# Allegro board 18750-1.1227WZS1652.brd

Outline 227 x 157 mm; copper layers: TOP, L2GND, L3, L4VCC, L5, L6, L7GND, BOTTOM. Coordinates in mm from the lower left corner of the outline.

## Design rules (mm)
constraint set DEFAULT: min track width 0.127, pair gap 0.102
net group 00_POWER_25M: nets PQ3802_1 PSID_DISABLE#_R_C
net group 00_POWER_1600M: nets XVDD_R1 XVDD_R2
net group DDR4_A_BA_40-MW: nets M_A_BA0 M_A_BA1
net group DDR4_A_BG_40-MW: nets M_A_BG0 M_A_BG1
net group DDR4_A_ODT: nets M_A_DIMA_ODT0 M_A_DIMA_ODT1
net group DDR4_B_BA_40-MW: nets M_B_BA0 M_B_BA1
net group DDR4_B_BG_40-MW: nets M_B_BG0 M_B_BG1
net group DDR4_B_ODT: nets M_B_DIMB_ODT0 M_B_DIMB_ODT1
net group DDR4_VREF_40: nets V_SM_VREF_CNTA V_SM_VREF_CNTB
net group MEM_SMBCLK: nets MEM_SMBCLK PCH_SMBCLK
net group MEM_SMBDATA: nets MEM_SMBDATA PCH_SMBDATA
net group PWR_CHG_CSONP-DIFF1: nets PWR_CHG_CSON_RR PWR_CHG_CSOP_RR
net group T8-MW: nets CMP_VIN0 CMP_VIN0_R
net group USB_CC_15M: nets USBC1_CC1_CONN USBC1_CC2_CONN
net group 00_POWER_5M: nets 3D3V_LAN_CT2 3V5V_CT1 3V5V_CT2 AON_CT_2 AUD_PC_BEEP AUD_PC_BEEP_C BEEP HDA_SPKR_R KBC_BEEP_R LPS_SW LPS_SW_A LPS_SW_C LPS_SW_D SPKR VGA_CT_1 VGA_NVVDD
net group 00_POWER_10M: nets 1D0V_VCCA_XTAL 1D0V_VCCAMPHYPLL 1D0V_VCCDSW +5V_AVDD +SDC_IN_SW_R1 BMON22 CNV_WT_RCOMP FP_3D3V GSENSOR_CS HW_ACAV_IN0 HW_ACAVIN_NB0 I_BATT LDO1_CAP LDO2_CAP LDO3_CAP MIC_CAP PWR_VGA_NVDD_SS PWR_VGA_NVVDD_VSEN PWR_VGA_NVVDD_VSNS/SS
net group 00_POWER_10M_POWER: nets 3D3V_GSEN2 3D3V_MUX 3D3V_MUX2 3D3V_MUX_VCC AC_IN#_G AD_OFF_R AMBER_LED_BAT BAT_AMBER BAT_WHITE LAN_LED0 LAN_LED0_Q LAN_LED0_R PD_VCCD PWR_1D05V_PFM# PWR_1D05V_SS PWR_1D05V_TON PWR_1D35V_BYP PWR_1D35V_IMAX PWR_3D3V_VOUT PWR_5V_VOUT PWR_CHG_ACIN PWR_CHG_ADP/ACIN PWR_CHG_AIN PWR_CHG_AIN_R PWR_CHG_AMON PWR_CHG_ASGATE PWR_CHG_ASGATE/NTC PWR_CHG_BATGONE PWR_CHG_CMRSC PWR_CHG_COMP PWR_CHG_COMP_R PWR_CHG_DCIN PWR_CHG_DCIN_R PWR_CHG_NTC PWR_CHG_OTGEN PWR_CHG_OTGPG PWR_CHG_PROG PWR_CHG_VBAT1 PWR_VCCGT_COMP PWR_VCCGT_COMP1 PWR_VCCGT_FCCM# PWR_VCCGT_FCCM#_RA PWR_VCCGT_FCCM#_RB PWR_VCCGT_IMON PWR_VCCGT_ISEN1 PWR_VCCGT_ISEN2 PWR_VCCGT_ISUMN PWR_VCCGT_ISUMN_P_1 PWR_VCCGT_ISUMN_P_2 PWR_VCCGT_ISUMN_RC PWR_VCCGT_ISUMNB PWR_VCCGT_ISUMP PWR_VCCGT_NTC PWR_VCCGT_NTC1 PWR_VCCGT_PWMA PWR_VCCGT_PWMA_RA PWR_VCCGT_PWMB PWR_VCCGT_PWMB_RA PWR_VCCGT_RTN PWR_VCCSA_COMP PWR_VCCSA_COMP_RC PWR_VCCSA_FCCM PWR_VCCSA_IMON PWR_VCCSA_ISUMN PWR_VCCSA_ISUMN_P_1 PWR_VCCSA_ISUMN_P_2 PWR_VCCSA_ISUMN_RC PWR_VCCSA_ISUMNB PWR_VCCSA_ISUMP PWR_VCCSA_PWM PWR_VCCSA_RTN PWR_VCORE_COMP PWR_VCORE_COMP1 PWR_VCORE_FCCM# PWR_VCORE_FCCM#_R PWR_VCORE_IMON PWR_VCORE_ISUMN PWR_VCORE_ISUMN_P_1 PWR_VCORE_ISUMN_P_2 PWR_VCORE_ISUMN_RC PWR_VCORE_ISUMNA PWR_VCORE_ISUMP PWR_VCORE_NTC PWR_VCORE_NTC1 PWR_VCORE_PROG1 PWR_VCORE_PROG2 PWR_VCORE_PWM PWR_VCORE_PWM_R PWR_VCORE_RTN PWR_VCORE_VR PWR_VDDQ_CS PWR_VDDQ_FB PWR_VDDQ_TON PWR_VDDQ_VDDQ PWR_VGA_CORE_EN# PWR_VGA_CORE_PSI PWR_VGA_CORE_VID PWR_VGA_NVVDD_REFADJ PWR_VGA_NVVDD_REFADJ_R PWR_VGA_NVVDD_REFIN PWR_VGA_NVVDD_REFIN_R PWR_VGA_NVVDD_TON PWR_VGA_NVVDD_TON_1 PWR_VGA_NVVDD_VREF PWR_VGA_NVVDD_VSEN_N PWR_VGA_NVVDD_VSEN_P VDD WHITE_LED_BAT
net group 00_POWER_15M_FB_POWER: nets PWR_1D05V_FB PWR_1D05V_FB_A PWR_1D8V_FB PWR_1D35V_VFB PWR_1D35V_VFB1 PWR_1V_VGA_FB PWR_2D5V_FB PWR_3D3V_FB PWR_3D3V_FB2 PWR_5V_FB PWR_5V_FB_A PWR_VCCGT_FB PWR_VCCGT_FB1 PWR_VCCGT_FB2 PWR_VCCGT_FB_RC PWR_VCCSA_FB PWR_VCCSA_FB1 PWR_VCCSA_FB2 PWR_VCCSA_FB_RC PWR_VCORE_FB PWR_VCORE_FB1 PWR_VCORE_FB2 PWR_VCORE_FB_RC
net group 00_POWER_20M: nets 1D8V_AVDD2 1D24V_VCCDPHY_EC 3D3V_RTC 3D3V_RTC_SYS 3D3V_SPIVCC1 3D3V_TPM 5V_IRLED +RTC_CELL_VBAT +RTC_VCC +V_VREF_PATH2 GPCPLL_AVDD VDD10 VID_PLLVDD VREF_CPU
net group 00_POWER_20M_20M_POWER: nets PWR_1D35V_BOOT_R PWR_3D3V_BOOT PWR_3D3V_BOOT_A PWR_5V_BOOT PWR_5V_BOOT_A PWR_CHG_ASGATE22 PWR_CHG_BGATE PWR_CHG_BGATE_22 PWR_CHG_BT2_R PWR_VCCGT_BOOTA PWR_VCCGT_BOOTA_RC PWR_VCCGT_BOOTB PWR_VCCGT_BOOTB_RC PWR_VCCGT_BOOTRA PWR_VCCGT_BOOTRB PWR_VCCGT_SNB1 PWR_VCCGT_SNB2 PWR_VCCSA_BST PWR_VCCSA_BST_RC PWR_VCORE_BOOT_RC PWR_VCORE_BOOTR PWR_VCORE_SNB PWR_VDDQ_BOOT PWR_VDDQ_BOOTA PWR_VDDQ_BOOTB PWR_VDDQ_SNB PWR_VGA_NVVDD_BOOT1_A PWR_VGA_NVVDD_BOOT2_A
net group 00_POWER_20M_POWER: nets 5V_AUX_S5 5V_VCONN_P1_CCG4 +5V_KB_BL CPVDD KB_BL_CTRL# PWR_5V_LDO PWR_VCCGT_VCCDA PWR_VCORE_VCC PWR_VCORE_VIN
net group 00_POWER_30M: nets +3V_1D8V_DVDD
net group 00_POWER_30M_20M_POWER: nets PWR_CHG_HG1_R PWR_CHG_HG2_R PWR_CHG_LGATE2 PWR_CHG_SNB
net group 00_POWER_40M: nets 5V_HDMI +1.8VALW_EC DC_IN_OFF FB_CAL_PD_VDDQ FB_CAL_PU_GND FB_CAL_TERM_GND PQ4348_D PU4348_G PWR_VDDQ_VTTREF
net group 00_POWER_80M: nets 1D8V_AON_S0_DISCHG 1D8V_VGA_S0_DISCHG 1D35V_VGA_S0_DISCHG VGA_CORE_DISCHG
net group 3D5MIL_NO_TP: nets FBA_MF1
net group AUDIO_8M: nets MIC2_VREFO
net group AUDIO_12MIL: nets CPVEE
net group AUDIO_12MIL(2): nets AUD_HP1_JACK_L AUD_HP1_JACK_L1 AUD_HP1_JACK_R AUD_HP1_JACK_R1 AUD_PORTA_L_HPMIC1 AUD_PORTA_R_HPMIC1
net group AUDIO_BEEP_10MIL: nets AUD_HPJD_N AUD_SENSE AUD_VREF CBN CBP JACK_PLUG JACK_PLUG_DET LINE1-L_C LINE1-L_R LINE1_L LINE1_R LINE1_VREFO LINE1_VREFO_D1 LINE1_VREFO_D2
net group AUDIO_BITCLK_50-MW: nets HDA_RST_N_CPU
net group AUDIO_SLEEVE_40MIL: nets SLEEVE_R
net group CLK_50-MWS: nets CLKIN_XTAL_LCP PULSAR_38P4M_REFCLK SUS_CLK SUSACK#_R SUSCLK_WLAN VIDEO_CLK_XTAL_SS
net group CNV: nets CNV_MFUART2_RXD CNV_MFUART2_TXD CNV_PA_BLANKING
net group COMP_20MIL: nets CFG_RCOMP SM_RCOMP_0 SM_RCOMP_1 SM_RCOMP_2
net group CPU_50-MWS: nets CMP_VOUT0 LPS_SW_R SM_DRAMRST#_CPU TS#_DIMM0_1 TS#_DIMM1_1 VGA_CORE_VID
net group CRT_AUX_CPU_N: nets CRT_AUX_CPU_N_R
net group CRT_AUX_CPU_P: nets CRT_AUX_CPU_P_R
net group CRT_DDI_TX_N0: nets DP2_DEMUX_OUT2_D0N
net group CRT_DDI_TX_P0: nets DP2_DEMUX_OUT2_D0P
net group DDR4_A_CMD_40-MW: nets M_A_A0 M_A_A1 M_A_A2 M_A_A3 M_A_A4 M_A_A5 M_A_A6 M_A_A7 M_A_A8 M_A_A9 M_A_A10 M_A_A11 M_A_A12 M_A_A13 M_A_A14 M_A_A15 M_A_A16 M_A_ACT_N M_A_ALERT_N M_A_PARITY
net group DDR4_A_DATA_00_50-MW: nets M_A_DQ0 M_A_DQ1 M_A_DQ2 M_A_DQ3 M_A_DQ4 M_A_DQ5 M_A_DQ6 M_A_DQ7
net group DDR4_A_DATA_01_50-MW: nets M_A_DQ8 M_A_DQ9 M_A_DQ10 M_A_DQ11 M_A_DQ12 M_A_DQ13 M_A_DQ14 M_A_DQ15
net group DDR4_A_DATA_02_50-MW: nets M_A_DQ16 M_A_DQ17 M_A_DQ18 M_A_DQ19 M_A_DQ20 M_A_DQ21 M_A_DQ22 M_A_DQ23
net group DDR4_A_DATA_03_50-MW: nets M_A_DQ24 M_A_DQ25 M_A_DQ26 M_A_DQ27 M_A_DQ28 M_A_DQ29 M_A_DQ30 M_A_DQ31
net group DDR4_A_DATA_04_50--MW: nets M_A_DQ32 M_A_DQ33 M_A_DQ34 M_A_DQ35 M_A_DQ36 M_A_DQ37 M_A_DQ38 M_A_DQ39
net group DDR4_A_DATA_05_50-MW: nets M_A_DQ40 M_A_DQ41 M_A_DQ42 M_A_DQ43 M_A_DQ44 M_A_DQ45 M_A_DQ46 M_A_DQ47
net group DDR4_A_DATA_06_50-MW: nets M_A_DQ48 M_A_DQ49 M_A_DQ50 M_A_DQ51 M_A_DQ52 M_A_DQ53 M_A_DQ54 M_A_DQ55
net group DDR4_A_DATA_07_50-MW: nets M_A_DQ56 M_A_DQ57 M_A_DQ58 M_A_DQ59 M_A_DQ60 M_A_DQ61 M_A_DQ62 M_A_DQ63
net group DDR4_B_CMD_40--MW: nets M_B_A0 M_B_A1 M_B_A2 M_B_A3 M_B_A4 M_B_A5 M_B_A6 M_B_A7 M_B_A8 M_B_A9 M_B_A10 M_B_A11 M_B_A12 M_B_A13 M_B_A14 M_B_A15 M_B_A16 M_B_ACT_N M_B_ALERT_N M_B_PARITY
net group DDR4_B_DATA_00_50-MW: nets M_B_DQ0 M_B_DQ1 M_B_DQ2 M_B_DQ3 M_B_DQ4 M_B_DQ5 M_B_DQ6 M_B_DQ7
net group DDR4_B_DATA_01_50-MW: nets M_B_DQ8 M_B_DQ9 M_B_DQ10 M_B_DQ11 M_B_DQ12 M_B_DQ13 M_B_DQ14 M_B_DQ15
net group DDR4_B_DATA_02_50-MW: nets M_B_DQ16 M_B_DQ17 M_B_DQ18 M_B_DQ19 M_B_DQ20 M_B_DQ21 M_B_DQ22 M_B_DQ23
net group DDR4_B_DATA_03_50-MW: nets M_B_DQ24 M_B_DQ25 M_B_DQ26 M_B_DQ27 M_B_DQ28 M_B_DQ29 M_B_DQ30 M_B_DQ31
net group DDR4_B_DATA_04_50-MW: nets M_B_DQ32 M_B_DQ33 M_B_DQ34 M_B_DQ35 M_B_DQ36 M_B_DQ37 M_B_DQ38 M_B_DQ39
net group DDR4_B_DATA_05_50-MW: nets M_B_DQ40 M_B_DQ41 M_B_DQ42 M_B_DQ43 M_B_DQ44 M_B_DQ45 M_B_DQ46 M_B_DQ47
net group DDR4_B_DATA_06_50-MW: nets M_B_DQ48 M_B_DQ49 M_B_DQ50 M_B_DQ51 M_B_DQ52 M_B_DQ53 M_B_DQ54 M_B_DQ55
net group DDR4_B_DATA_07_50-MW: nets M_B_DQ56 M_B_DQ57 M_B_DQ58 M_B_DQ59 M_B_DQ60 M_B_DQ61 M_B_DQ62 M_B_DQ63
net group DDR4_CKE: nets M_A_CKE0 M_A_CKE1 M_A_CS#0 M_A_CS#1 M_B_CKE0 M_B_CKE1 M_B_CS#0 M_B_CS#1
net group DIMM_SA: nets SA0_CHA_DIM0 SA0_CHB_DIM0 SA1_CHA_DIM0 SA1_CHB_DIM0 SA2_CHA_DIM0 SA2_CHB_DIM0
net group EPSI_50: nets ESPI_ALERT#
net group FBA_VREF: nets FBA0_VREFC FBA1_VREFC FBA_VREF_FET_L
net group GFX_PCIE_TX_C_N2: nets GFX_PCIE_TX_C_N2
net group GFX_PCIE_TX_C_P2: nets GFX_PCIE_TX_C_P2
net group GND: nets U9101_2_GND
net group KBC: nets KSI0 KSI1 KSI2 KSI3 KSI4 KSI5 KSI6 KSI7 KSO0 KSO1 KSO2 KSO3 KSO4 KSO5 KSO6 KSO7 KSO8 KSO9 KSO10 KSO11 KSO12 KSO13 KSO14 KSO15 KSO16
net group LAN_6M: nets FBA_MF0 FBA_SEN1 RSET
net group LAN_MDI0_N: nets MDO0-
net group LAN_MDI0_P: nets MDO0+
net group LAN_MDI1_N: nets MDO1-
net group LAN_MDI1_P: nets MDO1+
net group LAN_MDI2_N: nets MDO2-
net group LAN_MDI2_P: nets MDO2+
net group LAN_MDI3_N: nets MDO3-
net group LAN_MDI3_P: nets MDO3+
net group LED: nets BAT2_LED# CAP_LED# CAP_LED#_R PWR_LED# PWR_LED#_C PWR_LED#_Q PWR_LED#_R SATA_LED# SATA_LED#_D
net group LED_20MIL: nets C10_GATE CAP_LED CAP_LED_Q
net group OTHER_4MIL: nets 1D05V_S5_PWRGD 1D8V_AON_EN 1D8V_MAIN_EN 1D8V_MAIN_EN_D 1D8V_MAIN_EN_R 1D8V_MAIN_ENABLE 1D8V_VGA_DISC 1D35V_PGOOD 1D35V_VGA_EN# 1V_VGA_S0_EN 1V_VGA_S0_PG 3D3V_CAMERA_CT1 3D3V_TP_CT2 3V_5V_DSW_OK 3V_5V_EN 3V_5V_POK# 5V_VCONN_EN 20V_VCCPD_VBUS_R AC_DIS AC_PRESENT ACOK_IN_M AD_IA AD_OFF_L ALERT# ALWON AUX_EN_WOWL AUX_EN_WOWL_R AUX_ON BAT1_LED# BATT_WHITE_LED# BATT_WHITE_LED#_Q BKLT_CTRL BKLT_IN_EC BLON_OUT_C BLUETOOTH_EN BLUETOOTH_EN_R BOARD_ID BOARD_ID1 BPM_CPU_N0 BPM_CPU_N1 BPM_CPU_N2 BPM_CPU_N3 BREATH_LED# BT_PCMOUT_CLKREQ0 CAD_SNK_MUX CAM_EN CATERR#_CPU CCG4_FLIP# CCG4_I2C_INT# CCG4_ID_1 CFG0_DP_MUX CFG3 CFG4 CHG_AMBER_LED# CHG_AMBER_LED#_Q CHGR_PSYS_IMVP CLK_PCIE_LAN_REQ# CLK_PCIE_NVME_REQ# CLK_PCIE_PEG_REQ# CLK_PCIE_SD_REQ# CLK_PCIE_WLAN_REQ# CNVI_EN# CNVI_EN#_R CPU_DP1_HPD CPU_DP2_HPD CPU_DP_HPD_MUX CPU_DP_HPD_R CRT_DP_HPD CRT_DP_HPD_R CTL1 CTL2 CTL3 DBC_EN_R DBC_PANEL_EN DCBATOUT_LCD_PG DCBATOUT_LCD_PWRGD DDR4_DRAMRST# DGPU_HOLD_RST# DGPU_PWR_EN DGPU_PWR_EN_1 DGPU_PWR_EN_2 DGPU_PWROK DOCK_USB_EN_A DOCK_USB_EN_B DP2_HPD_CPU DPEQ0_A1 DPEQ1 EC_D_INHIB EDP_FHD_DET# EDP_FHD_DET#_R EDP_HPD EDP_HPD_CONN EDP_VDD_EN EQ0 EQ1 EXT_PWR_GATE# FALL_INT2 FBA_DEBUG0 FBA_DEBUG1 FFS_INT1 FFS_INT2 FFS_INT2_Q FLT_NXP3290 FP_EN# FPR_SCAN# GC6_FB_EN_GPU GC6_FB_EN_GPU_L GC6_FB_EN_GPU_R GC6_FB_EN_MCP GC6_THM_DIS GC6_THM_DIS#_EC GC6_THM_DIS#_PCH GPD11/LANPHYPC GPD_7 GPIO5_FRAME_LOCK# GPIO9_ALERT GPIO10_FBVREF GPIO11_LCD_VDD GPIO13_LCD_BLEN GPP_E23_STRAP GPP_H2_CLKREQ0 GPP_H21 GPP_H23 GPPC_H18_VCCIO_LPM GPU_CLKREQ# GPU_EVENT_GPU# GPU_EVENT_GPU#_R GPU_EVENT_MCP# GPU_PEX_RST# GPU_PEX_RST_HOLD GPU_PEX_RST_HOLD_GPU# GPU_ROM GSENSOR_SDO H_CPUPWRGD HDD_DET# HDD_DEVSLP HDD_DEVSLP_R HDMI_HPD_B HDMI_HPD_CON HOST_DEBUG_TX HOST_DEBUG_TX_CON HPDIN HW_ACAV_IN HW_ACAVIN_NB I2C_CTL_EN I2CEN I_ADP IC_DELAY ICSP_CLR ILIM_HI ILIM_LO ILIM_SEL INPUT3VSEL INT#_ITE8010 IO_DB_DET# IO_DB_DET#_EC IO_DB_DET#_GPPG5 IO_DB_DET#_R IR_CAM_DET# ISOLATE# IST_TRIG ITP_PMODE JIO3_PCIE_WAKE# KB_DET# KB_LED_BL_DET KB_LED_DET_C KB_LED_PWM KBC_PWRBTN# KBC_PWRBTN#_C L_BKLT_CTRL L_BKLT_EN L_BKLT_EN_L LAN_CABLE_DETECT_R_# LAN_WAKE# LANWAKE# LCD_BRIGHTNESS LCD_CBL_DET# LCD_TST LCD_TST_C LCD_VCC_TEST_EN LCDVDD_EN LCDVDD_PG LCDVDD_PWRGD LID_CL_SIO# LID_CLOSE#_C LOM_CABLE_DETECT# LOM_TCT M2_PCIE_LED# M2_SSD_PEDET MASK_SATA_LED# MCT0 MCT1 MCT2 MCT3 ME_FWP ME_FWP_R ME_SUS_PWR_ACK_R MESW1_B MODEL_ID MSATA_DEVSLP_R MUX_HPD_PD MUX_SAI MUX_SAO MUX_SBI MUX_SBO N12P_JTAG_TCK N12P_JTAG_TDI N12P_JTAG_TDO N12P_JTAG_TMS N12P_JTAG_TRST N12P_XTAL_OUTBUFF N92950396 NB_MUTE# NC_AUX_EN_WOWL_EC NRB_BIT NUVOTON_PP NVVDD_EN NVVDD_EN_1 NXP3290_FO NXP3290_ILIM NXP3290CAP OUT1_CA_DET OUT2_CA_DET OVERT_GPU# PANEL_BKEN PANEL_BKEN_EC PANEL_MONITOR PANEL_PWRGD_R PBAT_PRES1# PBAT_PRES# PC10 PC11 PC20 PC21 PCH_BATLOW# PCH_PLTRST# PCH_RSMRST# PCH_TPAN_VDD_EN PCH_WAKE# PCIE_LAN_WAKE# PCIE_WAKE# PD4403_A PD4403_K PD_SWD_CLK PD_VBUS_C_CTRL1 PD_VBUS_C_CTRL1_A PD_VBUS_C_CTRL1_R PD_VBUS_C_EN_A PD_VBUS_C_EN_B PD_VBUS_DISCHG PD_VBUS_DISCHG_N1 PD_XRES PDB_R PEQ PEX_TERMP PEX_TSTCLK_OUT PEX_TSTCLK_OUT# PIRQA# PLTRST#_CPU PM_LAN_ENABLE PM_RSMRST# PM_RSMRST#_M POWER_SW_IN# PQ4405_2 PQ4405_3 PQ4405_5 PQ4405_6 PQ4408_C PQ4408_E PQ4417_D PQ4417_G PQ4418_2 PQ4418_3 PQ4418_5 PQ4418_6 PRIM_PWRGD PROCHOT PROCHOT#_CPU PROCHOT#_CPU_R PROJECT_ID0 PROJECT_ID1 PROJECT_ID2 PROJECT_ID3 PTP_DIS# PURE_HW_SHUTDOWN# PWR_1D05V_EN PWR_1D8V_EN PWR_1D8V_PG PWR_1D35V_PGOOD PWR_2D5V_EN PWR_2D5V_PG PWR_3D3V_EN PWR_3D3V_EN1 PWR_5V_EN PWR_5V_EN1 PWR_BD_DET# PWR_CHG_ACOK PWR_CHG_PSYS PWR_LEVEL PWR_VDDQ_EN PWR_VDDQ_PG PWR_VGA_GDDR_EN PWR_VGA_GDDR_EN_L PWR_VGA_NVVDD_EN PWR_VGA_NVVDD_EN_R PWR_VGA_NVVDD_PG Q501_G Q5503_B Q5503_C Q5503_E Q5504_B Q5504_C Q5505_E Q6407_B Q6407_C RESET_OUT# RSMRST_PWRGD# RTC_3P3_EN_G RTC_DET# RTCRST_ON RUNPWROK SATA1_ODD_PRSNT# SATA_ODD_DA#_C SATA_ODD_PRSNT#_R SD_READ_MODE# SD_READ_MODE#_R SIO_EXT_SMI# SIO_EXT_WAKE# SIO_PWRBTN# SIO_RCIN# SIO_SLP_A# SIO_SLP_S0# SIO_SLP_S3# SIO_SLP_S4# SIO_SLP_S5# SKTOCC# SM_INTRUDER# SM_PGCNTL SM_PGCNTL_Q SSD2_DEVSLP SSD_DEVSLP SSD_DEVSLP_R SSD_SCP# SSEQ0_A0 SSEQ1 ST_GPIO ST_PP STRAP0 STRAP1 STRAP2 STRAP3 STRAP4 STRAP5 STRAP5_R STRAP_REF0_GND_N9 SW_PIN SYS_LED_MASK# SYS_PEX_RST_MON# SYS_PEX_RST_MON_GPU# SYS_PRES1# SYS_PWROK SYSPWR_PRES T_CRIT# TESTMODE THERM_SYS_SHDN# THERMTRIP#_CPU TOUCH_I2C_DET# TOUCH_PAD_INTR# TOUCH_PANEL_INTR# TOUCH_PANEL_PD# TOUCH_REPORT_SW TP_EN# TP_ON#_GATE TP_WAKE_KBC# TPAN_VDD_EN_R TPM_GPIO0 TPM_GPIO1 TPM_GPIO4 TPM_ID TPM_SPI_IRQ# TPS2544_FAULT# TPS70933_EN TPS70933_EN_G TS_INT# TS_VREF TYPEC_DCIN1_EN# USB2_ID USB2_VBUSSENSE USB_EN# USB_OC0# USB_OC1# USB_OC1#_R USB_OC2# USB_OC3# USB_POWERSHARE_VBUS_EN USB_PWR_SHR_EN_L# V0.85A_VID0 V0.85A_VID1 VBUS_P_CTRL VBUS_P_CTRL_R VCCDSW_ON VCCPD_VBUS_ACK VCCST_PWRGD_R VCCSTG_EN_R1 VCCSTU_EN_R VCI_IN1# VDDQ_PWRGD VGA_CORE_VID_R VGA_DB_DET# VGA_DB_DET#_R VGA_PWR_EN# VR_EN VR_RDY VRALERT# VRAM_ID1 VRAM_ID2 WIFI_RF_EN WIFI_RF_EN_R WLAN_EN# WWAN_BB_RST# WWAN_CLKREQ_CPU_N WWAN_DB_DET# WWAN_DB_DET#_R WWAN_FULL_PWR_EN WWAN_FULL_PWR_EN_D8 WWAN_FULL_PWR_EN_R WWAN_GPIO_PERST# WWAN_PCIE_WAKE_N
net group POWER_10M: nets FB_CLAM
net group REF10M: nets VR_CAP
net group SIGNAL_V_F_5MIL: nets 1D8V_S0_CT1 ACOK# CEXT EDP_RCOMP_CPU EMMC_RCOMP FAN1_PWM FAN1_TACH FAN_PWM1_C FAN_TACH1 FAN_TACH1_C FBA_ZQ0 FBA_ZQ1 GPU_PWR_LEVEL PWR_CHG_PROCHOT# PWR_VCORE_VRHOT# Q6205_Q REXT1 RTC_RST# SD_RCOMP SRTC_RST# V3D3_STB XCLK_BIASREF
net group SIGNAL_V_F_10MIL-2: nets PS_ID PS_ID_R1 VCCRTCEXT VCREF0
net group SIGNAL_V_F_25MIL: nets HDMI_PLL_GND
net group SMBUS: nets BT_PCMFRM_RSTN CCG4_I2C_SCL CCG4_I2C_SDA CLK_TP_SIO CPU_DP2_CTRL_CLK CPU_DP2_CTRL_DATA CPU_POPIRCOMP DAT_TP_SIO DMIC_CLK_EDP DMIC_DATA_EDP DMIC_PCH_CLK DMIC_PCH_DATA DMIC_SCL_CODEC DMIC_SCL_CODEC_R DMIC_SDA_CODEC GPP_H1_SFRM GPU_I2CA_SCL GPU_I2CA_SDA HDMI_SCL_R HDMI_SDA_R I2C0_SCL_TCH_PAD I2C0_SCL_TCH_PNL I2C0_SDA_TCH_PAD I2C0_SDA_TCH_PNL I2C1_SCL_R I2C1_SDA_R I2C_CLK I2C_CLK_PD I2C_CLK_PD_MUX I2C_DATA_PD I2C_DATA_PD_MUX I2C_SDA I2CB_SCL I2CB_SDA I2CC_SCL I2CC_SDA ICSP_CLK ICSP_DAT PBAT_CHG_SMBCLK PBAT_CHG_SMBDAT PBAT_SMBCLK1 PBAT_SMBDAT1 PCH_JTAG_TCK PCH_JTAG_TDI PCH_JTAG_TDO PCH_JTAG_TMS PCH_POPIRCOMP SMB_ALERT# SML0_ALERT# SML0_SMBCLK SML0_SMBDATA SML1ALERT# TPCLK_C TPDATA_C TYPEC_SMBCLK TYPEC_SMBDA UART_2_CRXD_DTXD UART_2_CRXD_DTXD_CON UART_2_CTXD_DRXD UART_2_CTXD_DRXD_CON USBCOMP
net group SPI_50-MWS: nets GPU_ROM_SCLK GPU_ROM_SI GPU_ROM_SO SPI_CS2#_IC SPI_CS_CPU_N0 SPI_CS_CPU_N1 SPI_CS_CPU_N2 SPI_IRQ#_TPM2
net group SVID: nets GPIO6_VGA_CORE_PSI H_PECI PECI_CPU VGA_CORE_PSI
net group USB3_USB30_TX_CMC_N: nets USB3_USB30_TX_CMC_N
net group USB3_USB30_TX_CMC_P: nets USB3_USB30_TX_CMC_P
net group VRAM_10M: nets FBA_SEN0
net group VRAM_DBI_45R: nets FBA_DQM0 FBA_DQM1 FBA_DQM2 FBA_DQM3 FBA_DQM4 FBA_DQM5 FBA_DQM6 FBA_DQM7
net group VRAM_DQ_45R: nets FBA_CLK0_MIDPT FBA_CLK1_MIDPT FBA_D0 FBA_D1 FBA_D2 FBA_D3 FBA_D4 FBA_D5 FBA_D6 FBA_D7 FBA_D8 FBA_D9 FBA_D10 FBA_D11 FBA_D12 FBA_D13 FBA_D14 FBA_D15 FBA_D16 FBA_D17 FBA_D18 FBA_D19 FBA_D20 FBA_D21 FBA_D22 FBA_D23 FBA_D24 FBA_D25 FBA_D26 FBA_D27 FBA_D28 FBA_D29 FBA_D30 FBA_D31 FBA_D32 FBA_D33 FBA_D34 FBA_D35 FBA_D36 FBA_D37 FBA_D38 FBA_D39 FBA_D40 FBA_D41 FBA_D42 FBA_D43 FBA_D44 FBA_D45 FBA_D46 FBA_D47 FBA_D48 FBA_D49 FBA_D50 FBA_D51 FBA_D52 FBA_D53 FBA_D54 FBA_D55 FBA_D56 FBA_D57 FBA_D58 FBA_D59 FBA_D60 FBA_D61 FBA_D62 FBA_D63
net group VRAM_EDC_45R: nets FBA_EDC0 FBA_EDC1 FBA_EDC2 FBA_EDC3 FBA_EDC4 FBA_EDC5 FBA_EDC6 FBA_EDC7
net group XDP: nets XDP_DBRESET# XDP_PRDY# XDP_PREQ# XDP_TCK_JTAGX XDP_TCLK XDP_TDI XDP_TDO_CPU XDP_TMS XDP_TRST#
net group XTAL-MW: nets 27MHZ_OUT_R LANXIN LANXOUT MEC_XTAL1_R MEC_XTAL2 XTL_24M_X1_CPU XTL_24M_X1_R XTL_24M_X2_CPU XTL_24M_X2_R XTL_32K_X1_CPU XTL_32K_X2_CPU

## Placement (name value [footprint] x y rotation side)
AFTP2601  AFTE14P-GP  [AFTE14P-75]  158.37 86.69 90 top
AFTP2602  AFTE14P-GP  [AFTE14P-75]  158.37 84.79 90 top
AFTP2603  AFTE14P-GP  [AFTE14P-75]  160.79 88.7 90 top
AFTP2604  AFTE14P-GP  [AFTE14P-75]  128.53 107.72 90 top
AFTP2901  AFTE14P-GP  [AFTE14P-75]  7.8 5.36 180 top
AFTP2902  AFTE14P-GP  [AFTE14P-75]  9.75 5.89 180 top
AFTP2903  AFTE14P-GP  [AFTE14P-75]  11.36 4.37 90 top
AFTP2904  AFTE14P-GP  [AFTE14P-75]  12.04 2.34 90 top
AFTP3201  AFTE14P-GP  [AFTE14P-75]  22.95 86.51 0 bottom
AFTP3202  AFTE14P-GP  [AFTE14P-75]  26.37 81.26 0 bottom
AFTP3204  AFTE14P-GP  [AFTE14P-75]  23.9 88.34 0 bottom
AFTP3205  AFTE14P-GP  [AFTE14P-75]  26.24 84.23 180 top
AFTP3206  AFTE14P-GP  [AFTE14P-75]  25.87 81.68 180 top
AFTP3207  AFTE14P-GP  [AFTE14P-75]  19.56 80.06 180 top
AFTP3208  AFTE14P-GP  [AFTE14P-75]  24.46 81.19 0 bottom
AFTP3209  AFTE14P-GP  [AFTE14P-75]  18.9 78.26 180 top
AFTP3502  AFTE14P-GP  [AFTE14P-75]  17.53 48.21 90 top
AFTP3503  AFTE14P-GP  [AFTE14P-75]  16.34 49.71 90 top
AFTP3507  AFTE14P-GP  [AFTE14P-75]  21.87 55.81 180 bottom
AFTP3508  AFTE14P-GP  [AFTE14P-75]  17.22 35.38 0 top
AFTP4302  AFTE14P-GP  [AFTE14P-75]  19.23 127.97 0 top
AFTP4303  AFTE14P-GP  [AFTE14P-75]  21.52 124.28 180 top
AFTP4304  AFTE14P-GP  [AFTE14P-75]  19.61 124.28 90 top
AFTP4306  AFTE14P-GP  [AFTE14P-75]  175.19 35.74 0 top
AFTP4307  AFTE14P-GP  [AFTE14P-75]  199.65 36.88 0 top
AFTP4309  AFTE14P-GP  [AFTE14P-75]  139.7 34.47 180 top
AFTP4310  AFTE14P-GP  [AFTE14P-75]  140.64 36.93 180 top
AFTP4311  AFTE14P-GP  [AFTE14P-75]  142.57 36.7 180 top
AFTP4312  AFTE14P-GP  [AFTE14P-75]  144.53 36.63 0 top
AFTP4313  AFTE14P-GP  [AFTE14P-75]  174.07 31.68 0 top
AFTP4315  AFTE14P-GP  [AFTE14P-75]  137.82 33.76 180 top
AFTP4401  AFTE14P-GP  [AFTE14P-75]  171.91 35.79 180 bottom
AFTP4402  AFTE14P-GP  [AFTE14P-75]  171.76 31.34 180 bottom
AFTP4403  AFTE14P-GP  [AFTE14P-75]  178.79 34.77 180 bottom
AFTP4404  AFTE14P-GP  [AFTE14P-75]  177.02 37.52 180 bottom
AFTP4405  AFTE14P-GP  [AFTE14P-75]  177.3 42.34 180 bottom
AFTP4406  AFTE14P-GP  [AFTE14P-75]  175.11 37.52 180 bottom
AFTP4407  AFTE14P-GP  [AFTE14P-75]  181.82 58.45 180 bottom
AFTP4408  AFTE14P-GP  [AFTE14P-75]  189.26 58.68 180 bottom
AFTP4501  AFTE14P-GP  [AFTE14P-75]  49 39.17 0 top
AFTP4502  AFTE14P-GP  [AFTE14P-75]  50.27 40.62 0 top
AFTP4601  AFTE14P-GP  [AFTE14P-75]  63.25 128.2 0 top
AFTP4602  AFTE14P-GP  [AFTE14P-75]  62.36 129.72 0 top
AFTP4603  AFTE14P-GP  [AFTE14P-75]  88.78 129.21 0 top
AFTP4604  AFTE14P-GP  [AFTE14P-75]  87.76 130.35 0 top
AFTP4605  AFTE14P-GP  [AFTE14P-75]  96.27 130.74 0 top
AFTP4606  AFTE14P-GP  [AFTE14P-75]  97.79 129.59 0 top
AFTP5001  AFTE14P-GP  [AFTE14P-75]  92.64 138.28 0 top
AFTP5501  AFTE14P-GP  [AFTE14P-75]  168.41 71.83 270 top
AFTP5502  AFTE14P-GP  [AFTE14P-75]  170.97 34.44 270 top
AFTP5503  AFTE14P-GP  [AFTE14P-75]  178.06 70.31 270 top
AFTP5504  AFTE14P-GP  [AFTE14P-75]  169.45 35.71 270 top
AFTP5505  AFTE14P-GP  [AFTE14P-75]  168.68 41.66 270 top
AFTP5506  AFTE14P-GP  [AFTE14P-75]  167.57 35.03 270 top
AFTP5509  AFTE14P-GP  [AFTE14P-75]  212.12 42.8 270 top
AFTP5510  AFTE14P-GP  [AFTE14P-75]  213.97 44.88 270 top
AFTP5511  AFTE14P-GP  [AFTE14P-75]  215.4 43.49 270 top
AFTP5512  AFTE14P-GP  [AFTE14P-75]  218.98 42.01 270 top
AFTP5513  AFTE14P-GP  [AFTE14P-75]  182.1 69.93 270 top
AFTP5514  AFTE14P-GP  [AFTE14P-75]  136.91 35.46 270 top
AFTP5517  AFTE14P-GP  [AFTE14P-75]  215.17 41.58 270 top
AFTP5521  AFTE14P-GP  [AFTE14P-75]  220.09 39.04 270 top
AFTP5522  AFTE14P-GP  [AFTE14P-75]  214.3 63.32 270 top
AFTP5523  AFTE14P-GP  [AFTE14P-75]  218.19 38.96 270 top
AFTP5525  AFTE14P-GP  [AFTE14P-75]  219.21 37.34 270 top
AFTP5601  AFTE14P-GP  [AFTE14P-75]  203.08 62.54 0 top
AFTP5602  AFTE14P-GP  [AFTE14P-75]  175.82 47.68 0 top
AFTP6001  AFTE14P-GP  [AFTE14P-75]  187.43 41.63 0 top
AFTP6002  AFTE14P-GP  [AFTE14P-75]  191.52 41.96 0 top
AFTP6003  AFTE14P-GP  [AFTE14P-75]  189.31 40.92 0 top
AFTP6004  AFTE14P-GP  [AFTE14P-75]  187.4 39.68 0 top
AFTP6005  AFTE14P-GP  [AFTE14P-75]  186.06 38.13 0 top
AFTP6006  AFTE14P-GP  [AFTE14P-75]  183.39 34.72 0 top
AFTP6108  AFTE14P-GP  [AFTE14P-75]  42.52 103.1 180 top
AFTP6109  AFTE14P-GP  [AFTE14P-75]  42.76 96.07 0 top
AFTP6110  AFTE14P-GP  [AFTE14P-75]  41.79 101.32 180 top
AFTP6111  AFTE14P-GP  [AFTE14P-75]  29.75 97.74 0 top
AFTP6112  AFTE14P-GP  [AFTE14P-75]  40.67 103.81 180 top
AFTP6113  AFTE14P-GP  [AFTE14P-75]  31.5 101.65 90 top
AFTP6114  AFTE14P-GP  [AFTE14P-75]  30.13 95.86 0 top
AFTP6115  AFTE14P-GP  [AFTE14P-75]  41.25 94.74 180 top
AFTP6401  AFTE14P-GP  [AFTE14P-75]  210.06 56.85 270 top
AFTP6402  TPAD14-OP-GP  [TPAD14-OP]  210.57 58.62 0 top
AFTP6403  AFTE14P-GP  [AFTE14P-75]  206.2 54.76 270 top
AFTP6404  AFTE14P-GP  [AFTE14P-75]  208.44 55.83 270 top
AFTP6407  AFTE14P-GP  [AFTE14P-75]  213.64 56.49 0 top
AFTP6408  AFTE14P-GP  [AFTE14P-75]  211.48 60.28 0 top
AFTP6501  AFTE14P-GP  [AFTE14P-75]  107.93 35.79 0 top
AFTP6524  AFTE14P-GP  [AFTE14P-75]  108.72 33.83 180 top
AFTP6525  AFTE14P-GP  [AFTE14P-75]  106.51 37.16 0 top
AFTP6526  AFTE14P-GP  [AFTE14P-75]  107.19 32.49 0 top
AFTP6527  AFTE14P-GP  [AFTE14P-75]  104.52 33.71 0 top
AFTP6528  AFTE14P-GP  [AFTE14P-75]  106.3 34.47 0 top
AFTP6529  AFTE14P-GP  [AFTE14P-75]  100.46 28.75 0 top
AFTP6530  AFTE14P-GP  [AFTE14P-75]  110.62 33.83 0 top
AFTP6531  AFTE14P-GP  [AFTE14P-75]  74.81 35.69 180 top
AFTP6537  AFTE14P-GP  [AFTE14P-75]  79.68 32.38 0 top
AFTP6541  AFTE14P-GP  [AFTE14P-75]  76.08 34.24 0 top
AFTP6542  AFTE14P-GP  [AFTE14P-75]  56.77 29.01 0 top
AFTP6543  AFTE14P-GP  [AFTE14P-75]  57.94 31.12 0 top
AFTP6544  AFTE14P-GP  [AFTE14P-75]  58.78 35.82 0 top
AFTP6545  AFTE14P-GP  [AFTE14P-75]  59.9 31.12 0 top
AFTP6546  AFTE14P-GP  [AFTE14P-75]  59.46 34.01 0 top
AFTP6547  AFTE14P-GP  [AFTE14P-75]  60.91 32.74 0 top
AFTP6548  AFTE14P-GP  [AFTE14P-75]  61.95 31.12 0 top
AFTP6549  AFTE14P-GP  [AFTE14P-75]  62.87 32.79 0 top
AFTP6550  AFTE14P-GP  [AFTE14P-75]  61.29 34.62 0 top
AFTP6551  AFTE14P-GP  [AFTE14P-75]  63.88 31.14 0 top
AFTP6552  AFTE14P-GP  [AFTE14P-75]  65.05 32.69 0 top
AFTP6553  AFTE14P-GP  [AFTE14P-75]  64.67 34.67 0 top
AFTP6554  AFTE14P-GP  [AFTE14P-75]  66.25 31.14 0 top
AFTP6555  AFTE14P-GP  [AFTE14P-75]  67.21 32.79 0 top
AFTP6556  AFTE14P-GP  [AFTE14P-75]  69.5 32.69 0 top
AFTP6557  AFTE14P-GP  [AFTE14P-75]  73.08 31.17 0 top
AFTP6558  AFTE14P-GP  [AFTE14P-75]  68.28 31.19 0 top
AFTP6559  AFTE14P-GP  [AFTE14P-75]  67.85 35.03 0 top
AFTP6560  AFTE14P-GP  [AFTE14P-75]  70.74 31.24 0 top
AFTP6561  AFTE14P-GP  [AFTE14P-75]  69.8 34.88 0 top
AFTP6562  AFTE14P-GP  [AFTE14P-75]  72.06 32.82 0 top
AFTP6563  AFTE14P-GP  [AFTE14P-75]  74.02 32.84 0 top
AFTP6564  AFTE14P-GP  [AFTE14P-75]  71.71 34.8 0 top
AFTP6565  AFTE14P-GP  [AFTE14P-75]  75.01 31.19 0 top
AFTP6566  AFTE14P-GP  [AFTE14P-75]  75.97 29.54 0 top
AFTP6567  AFTE14P-GP  [AFTE14P-75]  57.56 34.29 0 top
AFTP6609  AFTE14P-GP  [AFTE14P-75]  127 84.51 180 bottom
AFTP6610  AFTE14P-GP  [AFTE14P-75]  164.95 41.61 0 top
AFTP6611  AFTE14P-GP  [AFTE14P-75]  128.07 114.43 0 top
AFTP6613  AFTE14P-GP  [AFTE14P-75]  201.68 39.07 0 top
AFTP6614  AFTE14P-GP  [AFTE14P-75]  198.5 38.91 0 top
AFTP6615  AFTE14P-GP  [AFTE14P-75]  197.74 36.88 0 top
AFTP6801  AFTE14P-GP  [AFTE14P-75]  17.12 43.77 0 top
AFTP6802  AFTE14P-GP  [AFTE14P-75]  17.12 41.86 0 top
AFTP6803  AFTE14P-GP  [AFTE14P-75]  17.91 40.11 0 top
AFTP7101  AFTE14P-GP  [AFTE14P-75]  15.88 112.47 0 top
AFTP7102  AFTE14P-GP  [AFTE14P-75]  16.79 119.28 0 top
AFTP7301  AFTE14P-GP  [AFTE14P-75]  44.5 127.84 0 top
AFTP7302  AFTE14P-GP  [AFTE14P-75]  10.54 116.26 0 top
AFTP7303  AFTE14P-GP  [AFTE14P-75]  9.4 123.75 0 top
AFTP7304  AFTE14P-GP  [AFTE14P-75]  27.38 117.76 180 bottom
AFTP9201  AFTE14P-GP  [AFTE14P-75]  213.92 65.2 0 top
AFTP9204  AFTE14P-GP  [AFTE14P-75]  133.06 39.57 0 top
BATT1  ACES-CON10-10-GP-U  [88231-1001-LP]  139.7 34 180 bottom
BIOS1  MX25L12872FM2I-10G-GP  [SOIC8-1H86]  130.85 85.12 0 bottom
BIOS2  MX25L6473FZNI-08G-3-GP  [DFN8A5060-G4135H32]  135.66 85.02 180 top
C501  SCD1U16V2KX-3DLGP  [C402H22]  58.65 38.91 0 top
C801  SC1U6D3V1MX-GP  [C0201H14]  91.44 117.04 90 bottom
C802  SC1U6D3V1MX-GP  [C0201H14]  78.49 114.53 270 bottom
C803  SC1U6D3V1MX-GP  [C0201H14]  101.58 72.7 0 top
C804  SC1U6D3V1MX-GP  [C0201H14]  54.05 49.18 180 top
C805  SCD1U16V2KX-3DLGP  [C402H22]  97.03 117.05 270 top
C806  SC1U6D3V1MX-GP  [C0201H14]  97.03 116.28 270 top
C807  SC22U6D3V3MX-1-DL-GP  [C603H40]  97.18 118.04 90 top
C1102  SC1U6D3V1MX-GP  [C0201H14]  69.85 102.13 0 top
C1103  SC1U6D3V1MX-GP  [C0201H14]  65.73 94.95 270 top
C1104  SC1U6D3V1MX-GP  [C0201H14]  70.23 105.02 0 top
C1105  SC1U6D3V1MX-GP  [C0201H14]  67.71 100.14 0 top
C1106  SC1U6D3V1MX-GP  [C0201H14]  75.83 100.8 90 top
C1107  SC1U6D3V1MX-GP  [C0201H14]  72.52 101.78 90 top
C1108  SC1U6D3V1MX-GP  [C0201H14]  96.62 90.83 180 top
C1109  SC1U6D3V1MX-GP  [C0201H14]  85.35 90.86 0 top
C1110  SC1U6D3V1MX-GP  [C0201H14]  95.86 90.83 180 top
C1111  SC1U6D3V1MX-GP  [C0201H14]  84.56 90.86 0 top
C1112  SC22U6D3V3MX-1-DL-GP  [C603H40]  98.3 121.39 270 top
C1113  SC22U6D3V3MX-1-DL-GP  [C603H40]  111.99 89.49 180 top
C1114  SC1U6D3V1MX-GP  [C0201H14]  100.41 99.42 270 top
C1115  SC22U6D3V3MX-1-DL-GP  [C603H40]  106.37 115.4 270 top
C1116  SC1U6D3V1MX-GP  [C0201H14]  113.34 100.03 0 top
C1117  SC1U6D3V1MX-GP  [C0201H14]  98.91 116.77 270 top
C1118  SC22U6D3V3MX-1-DL-GP  [C603H40]  98.3 123.73 270 top
C1119  SC1U6D3V1MX-GP  [C0201H14]  98.89 118.38 270 top
C1120  SC10U6D3V3MX-DL-GP  [C603H36]  98.3 122.56 270 top
C1121  SC1U6D3V1MX-GP  [C0201H14]  100.34 94.69 270 top
C1122  SC22U6D3V3MX-1-DL-GP  [C603H40]  112.95 98.31 180 top
C1123  SC10U6D3V3MX-DL-GP  [C603H36]  113.26 89.49 180 top
C1128  SC22U6D3V3MX-1-DL-GP  [C603H40]  98.3 120.22 270 top
C1129  SC22U6D3V3MX-1-DL-GP  [C603H40]  98.29 124.92 270 top
C1130  SC22U6D3V3MX-1-DL-GP  [C603H40]  74.17 76.13 180 top
C1131  SC22U6D3V3MX-1-DL-GP  [C603H40]  140.72 51.13 180 top
C1132  SC22U6D3V3MX-1-DL-GP  [C603H40]  135.92 51.13 180 top
C1133  SC22U6D3V3MX-1-DL-GP  [C603H40]  107.25 127.66 270 top
C1134  SC22U6D3V3MX-1-DL-GP  [C603H40]  109.1 125.28 90 top
C1135  SC22U6D3V3MX-1-DL-GP  [C603H40]  107.6 126.49 270 top
C1136  SC10U6D3V3MX-DL-GP  [C603H36]  83.65 76.18 180 top
C1137  SC10U6D3V3MX-DL-GP  [C603H36]  91.16 76.23 180 top
C1138  SC10U6D3V3MX-DL-GP  [C603H36]  87.02 76.05 180 top
C1139  SCD1U16V2KX-3DLGP  [C402H22]  124.06 49.25 0 top
C1140  SCD1U16V2KX-3DLGP  [C402H22]  92.46 46.92 0 top
C1141  SCD1U16V2KX-3DLGP  [C402H22]  65.2 48.24 0 top
C1142  SCD1U16V2KX-3DLGP  [C402H22]  131.07 50.62 0 top
C1202  SC10U6D3V3MX-GP  [C603H38]  134.72 51.13 180 top
C1203  SC10U6D3V3MX-GP  [C603H38]  139.5 51.13 180 top
C1204  SC10U6D3V3MX-GP  [C603H38]  132.34 51.13 180 top
C1205  SC10U6D3V3MX-GP  [C603H38]  133.53 51.13 180 top
C1206  SC10U6D3V3MX-GP  [C603H38]  137.13 51.13 180 top
C1207  SC1U6D3V1MX-GP  [C0201H14]  97.06 48.59 0 top
C1208  SC10U6D3V3MX-GP  [C603H38]  74.22 40.11 180 bottom
C1209  SC10U6D3V3MX-GP  [C603H38]  141.91 51.13 180 top
C1210  SC10U6D3V3MX-GP  [C603H38]  138.31 51.13 180 top
C1214  SC1U6D3V1MX-GP  [C0201H14]  132.06 42.93 90 top
C1215  SC1U6D3V1MX-GP  [C0201H14]  141.91 43.31 90 top
C1216  SC1U6D3V1MX-GP  [C0201H14]  141.1 49.05 0 top
C1217  SC1U6D3V1MX-GP  [C0201H14]  152.53 45.01 0 top
C1218  SC1U6D3V1MX-GP  [C0201H14]  161.98 44.76 180 top
C1219  SC1U6D3V1MX-GP  [C0201H14]  133.2 43.28 0 top
C1220  SC1U6D3V1MX-GP  [C0201H14]  136.07 45.62 180 top
C1221  SC1U6D3V1MX-GP  [C0201H14]  139.5 45.21 180 top
C1222  SCD022U16V2KX-3GP  [C402H22]  73.56 40.06 270 top
C1223  SC4D7U6D3V3KX-GP  [C603H36]  97.13 40.82 270 bottom
C1225  SC1U6D3V1MX-GP  [C0201H14]  98.76 40.64 0 top
C1226  SC1U6D3V1MX-GP  [C0201H14]  97.95 40.64 0 top
C1227  SC4D7U6D3V3KX-GP  [C603H36]  95.58 39.63 90 bottom
C1228  SCD1U16V2KX-L-GP  [C402H22]  96.12 47.55 180 top
C1229  SCD1U16V2KX-3DLGP  [C402H22]  72.37 40.54 0 top
C1231  SC10U6D3V2MX-2-GP  [C402-TO0D2H28]  97.92 48.49 0 top
C1301  SCD1U16V2KX-3DLGP  [C402H22]  149 43.56 90 top
C1303  SC10U6D3V3MX-GP  [C603H38]  70.62 76.25 180 top
C1304  SC10U6D3V2MX-2-GP  [C402-TO0D2H28]  59.11 49.05 0 top
C1305  SC10U6D3V3MX-GP  [C603H38]  73.03 40.11 180 bottom
C1306  SC10U6D3V3MX-GP  [C603H38]  137.11 40.64 90 bottom
C1307  SC10U6D3V2MX-2-GP  [C402-TO0D2H28]  67.85 48.08 0 top
C1308  SC10U6D3V3MX-GP  [C603H38]  71.81 40.12 180 bottom
C1309  SC10U6D3V2MX-2-GP  [C402-TO0D2H28]  63.17 49.4 0 top
C1310  SC10U6D3V3MX-GP  [C603H38]  75.42 40.11 180 bottom
C1311  SC10U6D3V2MX-2-GP  [C402-TO0D2H28]  173.79 50.27 90 top
C1313  SC1U6D3V1MX-GP  [C0201H14]  173.76 49.38 90 top
C1315  SC1U6D3V1MX-GP  [C0201H14]  85.78 45.95 0 top
C1316  SC1U6D3V1MX-GP  [C0201H14]  37.36 45.77 0 top
C1317  SC1U6D3V1MX-GP  [C0201H14]  48.97 49 180 top
C1318  SC1U6D3V1MX-GP  [C0201H14]  34.76 45.95 0 top
C1319  SC1U6D3V1MX-GP  [C0201H14]  42.75 44.58 180 top
C1320  SC1U6D3V1MX-GP  [C0201H14]  61.34 45.77 180 top
C1321  SC1U6D3V1MX-GP  [C0201H14]  74.07 49.66 0 top
C1322  SC1U6D3V1MX-GP  [C0201H14]  58.3 45.14 180 top
C1323  SCD022U16V2KX-3GP  [C402H22]  145.55 43.51 270 top
C1324  SC10U6D3V2MX-2-GP  [C402-TO0D2H28]  174.95 44.31 90 top
C1325  SC10U6D3V2MX-2-GP  [C402-TO0D2H28]  174.95 43.4 90 top
C1326  SC1U6D3V1MX-GP  [C0201H14]  175.27 45.96 90 top
C1327  SC1U6D3V1MX-GP  [C0201H14]  174.95 45.19 90 top
C1328  SCD1U16V2KX-L-GP  [C402H22]  173.89 51.52 0 top
C1329  SC2D2U6D3V2MX-DL-GP  [C402H22]  174.67 51.52 0 top
C1603  SCD22U10V2KX-1GP  [C402H22]  109.14 117.41 90 bottom
C1604  SCD22U10V2KX-1GP  [C402H22]  109.14 116.65 90 bottom
C1605  SCD22U10V2KX-1GP  [C402H22]  115.31 118.11 135 bottom
C1606  SCD22U10V2KX-1GP  [C402H22]  114.77 118.66 135 bottom
C1607  SCD22U10V2KX-1GP  [C402H22]  114.92 120.73 135 bottom
C1608  SCD22U10V2KX-1GP  [C402H22]  115.47 120.17 135 bottom
C1611  SCD22U10V2KX-1GP  [C402H22]  106.76 117.74 90 bottom
C1612  SCD22U10V2KX-1GP  [C402H22]  106.76 118.5 90 bottom
C1701  SC220P50V2KX-3DLGP  [C402H22]  160.79 78.79 0 bottom
C1702  SCD22U10V2KX-1GP  [C402H22]  103.63 90.72 270 top
C1703  SCD22U10V2KX-1GP  [C402H22]  86.85 40.17 270 top
C1711  SCD1U16V2KX-3DLGP  [C402H22]  95.73 114.53 270 bottom
C1803  SC12P50V2JN-DL-GP  [C402H22]  120.75 76.73 180 top
C1804  SC12P50V2JN-DL-GP  [C402H22]  120.75 74.68 0 top
C1805  SC1U6D3V1MX-GP  [C0201H14]  166.91 66.33 270 top
C1806  SC1U6D3V1MX-GP  [C0201H14]  169 66.88 90 top
C1807  SC15P50V2JN-DL-GP  [C402H22]  120.2 115.32 90 bottom
C1808  SC15P50V2JN-DL-GP  [C402H22]  116.94 115.29 270 bottom
C1809  SC2D2P50V2CC-DLGP  [C402H22]  122.66 114.48 90 bottom
C2201  SCD1U16V2KX-3DLGP  [C402H22]  100.64 92.9 180 top
C2202  SC1U6D3V1MX-GP  [C0201H14]  105.93 95.3 0 top
C2203  SC1U6D3V1MX-GP  [C0201H14]  105.92 93.93 180 top
C2204  SC1U6D3V1MX-GP  [C0201H14]  107.19 93.93 180 top
C2205  SC1U6D3V1MX-GP  [C0201H14]  106.56 93.93 180 top
C2206  SCD1U16V2KX-3DLGP  [C402H22]  106.94 92.1 270 top
C2207  SCD1U16V2KX-3DLGP  [C402H22]  104.6 92.46 0 top
C2208  SC47U6D3V3MX-2-GP  [C603H40]  104.88 116.58 90 top
C2209  SC1U6D3V1MX-GP  [C0201H14]  104.63 115.72 90 top
C2210  SC1U6D3V1MX-GP  [C0201H14]  107.11 97.38 180 top
C2211  SC1U6D3V1MX-GP  [C0201H14]  113.98 97.64 180 top
C2212  SC1U6D3V1MX-GP  [C0201H14]  98.91 115.16 270 top
C2213  SC1U6D3V1MX-GP  [C0201H14]  103.15 91.72 90 top
C2214  SC1U6D3V1MX-GP  [C0201H14]  103.3 95.63 0 top
C2215  SC1U6D3V1MX-GP  [C0201H14]  98.9 115.97 270 top
C2216  SC1U6D3V1MX-GP  [C0201H14]  100.32 95.49 270 top
C2217  SC1U6D3V1MX-GP  [C0201H14]  98.91 117.56 270 top
C2218  SC4D7U6D3V3KX-DLGP  [C603H36]  112.71 91.26 270 top
C2219  SC1U6D3V1MX-GP  [C0201H14]  115.17 102.95 180 top
C2220  SC22U6D3V3MX-1-DL-GP  [C603H40]  104.75 98.16 90 top
C2221  SCD1U16V2KX-3DLGP  [C402H22]  164.95 66.68 0 top
C2222  SC1U6D3V1MX-GP  [C0201H14]  165.74 66.68 0 top
C2223  SC1U6D3V1MX-GP  [C0201H14]  114.1 100.03 0 top
C2224  SC1U6D3V1MX-GP  [C0201H14]  144.44 71.33 0 top
C2225  SC1U6D3V1MX-GP  [C0201H14]  115.12 89.38 90 top
C2226  SC1U6D3V1MX-GP  [C0201H14]  103.94 92.36 0 top
C2227  SC1U6D3V1MX-GP  [C0201H14]  105.26 92.41 0 top
C2228  SC1U6D3V1MX-GP  [C0201H14]  105.9 92.41 0 top
C2229  SC1U6D3V1MX-GP  [C0201H14]  102.14 91.72 90 top
C2230  SC1U6D3V1MX-GP  [C0201H14]  102.64 92.81 90 top
C2231  SC47U6D3V3MX-2-GP  [C603H40]  114.2 102.74 180 top
C2405  SC100P50V2JN-3GP  [C402H22]  41.53 72.04 90 top
C2406  SCD1U16V2KX-3DLGP  [C402H22]  41.53 72.8 90 top
C2407  SCD1U16V2KX-3DLGP  [C402H22]  39.14 77.22 180 top
C2408  SCD1U16V2KX-3DLGP  [C402H22]  33.33 76.63 180 top
C2409  SCD01U25V2KX-3DLGP  [C402H22]  23.37 63.3 90 bottom
C2410  SCD1U16V2KX-3DLGP  [C402H22]  38.56 57 270 top
C2411  SCD1U16V2KX-3DLGP  [C402H22]  19.56 63.76 90 bottom
C2412  SCD1U16V2KX-3DLGP  [C402H22]  29.47 76.13 270 top
C2413  SCD1U16V2KX-3DLGP  [C402H22]  41.68 66.07 0 top
C2414  SCD1U16V2KX-3DLGP  [C402H22]  36.68 75.87 0 top
C2416  SCD1U16V2KX-3DLGP  [C402H22]  17.78 68.2 270 top
C2418  SC1U6D3V1MX-GP  [C0201H14]  23.93 65.86 90 bottom
C2420  SCD1U16V2KX-3DLGP  [C402H22]  29.75 56.21 90 top
C2421  SCD1U16V2KX-3DLGP  [C402H22]  17.78 68.96 270 top
C2422  SCD1U16V2KX-3DLGP  [C402H22]  20.75 70.89 270 top
C2423  SCD1U16V2KX-3DLGP  [C402H22]  32.95 57.15 270 top
C2424  SC18P50V2JN-1DLGP  [C402H22]  26.24 76.1 90 top
C2425  SC18P50V2JN-1DLGP  [C402H22]  27.79 76.1 270 top
C2426  SC2D2U10V3KX-1DLGP-U  [C603H36]  23.78 76.18 90 top
C2428  SCD1U16V2KX-3DLGP  [C402H22]  26.24 71.81 0 bottom
C2429  SCD1U16V2KX-3DLGP  [C402H22]  23.02 65.38 0 bottom
C2431  SC2200P50V2KX-2GP  [C402H22]  30.69 76.68 180 top
C2432  SCD1U16V2KX-3DLGP  [C402H22]  46.87 56.26 135 top
C2435  SC2200P50V2KX-2GP  [C402H22]  37.57 77.27 180 top
C2501  SC10U6D3V3MX-DL-GP  [C603H36]  129.16 79.2 180 bottom
C2502  SCD1U16V2KX-3DLGP  [C402H22]  128.17 78.77 180 bottom
C2503  SCD47U25V3KX-1GP  [C603H36]  162.21 91.37 270 bottom
C2517  SCD022U16V2KX-3DLGP  [C402H22]  165.91 91.4 0 top
C2525  SC1U6D3V1MX-GP  [C0201H14]  155.1 91.44 90 bottom
C2601  SC10U6D3V2MX-GP-U  [C402-TO0D2H28]  127.28 112.52 315 top
C2602  SCD1U16V2KX-3GP  [C402H22]  127.99 111.35 315 top
C2603  SC2200P50V2KX-2DLGP  [C402H22]  158.65 88.15 0 top
C2604  SC4D7U6D3V3KX-DLGP  [C603H36]  162.56 87.17 270 top
C2605  SCD1U25V2KX-1-DL-GP  [C402H22]  159.41 88.15 0 top
C2606  SC470P50V3JN-2GP  [C603H36]  167.39 78.67 90 bottom
C2607  SC2200P50V2KX-2DLGP  [C402H22]  121.28 118.79 315 top
C2610  SCD1U16V2KX-3DLGP  [C402H22]  129.3 108.34 135 bottom
C2612  SCD1U16V2KX-3GP  [C402H22]  16.92 63.15 180 bottom
C2613  SC100P50V2JN-3DLGP  [C402H22]  17.68 63.15 180 bottom
C2614  SCD1U16V2KX-3DLGP  [C402H22]  128.38 109.3 135 bottom
C2702  SC10U6D3V2MX-2-GP  [C402-TO0D2H28]  23.65 8.59 180 top
C2703  SC10U6D3V2MX-2-GP  [C402-TO0D2H28]  22.96 10.49 270 top
C2704  SCD1U16V2KX-3GP  [C402H22]  30.53 7.82 270 top
C2705  SC2D2U10V3KX-1DLGP-U  [C603H36]  30.94 8.82 270 top
C2706  SCD1U16V2KX-3GP  [C402H22]  22.51 11.86 180 top
C2707  SC10U6D3V3MX-DL-GP  [C603H36]  20.93 11.2 270 top
C2708  SC2D2U10V3KX-1DLGP-U  [C603H36]  32.72 7.77 180 top
C2709  SC2D2U10V3KX-1DLGP-U  [C603H36]  29.16 7.19 0 top
C2710  SC10U6D3V2MX-2-GP  [C402-TO0D2H28]  33.63 10.95 90 top
C2711  SC10U6D3V2MX-2-GP  [C402-TO0D2H28]  33.63 10.03 90 top
C2713  SC10U10V3MX-GP-U  [C603H38]  34.55 12.93 90 top
C2714  SCD1U16V2KX-3GP  [C402H22]  32.46 12.57 180 top
C2715  SC10U6D3V2MX-2-GP  [C402-TO0D2H28]  17.43 14.07 0 top
C2717  SC10U10V3MX-GP-U  [C603H38]  34.55 14.2 90 top
C2718  SCD1U16V2KX-3GP  [C402H22]  32.41 14.07 0 top
C2720  SC10U6D3V3MX-GP  [C603H38]  29.92 19.36 90 top
C2721  SCD1U16V2KX-3GP  [C402H22]  30.66 17.63 90 top
C2722  SC10U6D3V3MX-GP  [C603H38]  25.89 18.95 180 top
C2723  SCD1U16V2KX-3GP  [C402H22]  30.69 18.39 90 top
C2735  SCD1U16V2KX-3DLGP  [C402H22]  22.72 17.92 45 top
C2736  SC10U6D3V3MX-GP  [C603H38]  29.87 21.69 90 top
C2740  SC2D2U10V3KX-L-GP  [C603H36]  29.92 20.52 90 top
C2741  SCD1U16V2KX-3GP  [C402H22]  24.77 17.76 180 top
C2902  SC10U6D3V3MX-GP  [C603H38]  19.74 18.34 180 top
C2907  SC4D7U6D3V3KX-DLGP  [C603H36]  20.58 12.63 270 top
C2908  SC4D7U6D3V3KX-DLGP  [C603H36]  20.58 13.82 270 top
C3102  SCD1U16V2KX-3DLGP  [C402H22]  48.26 79.97 180 top
C3103  SCD1U16V2KX-3DLGP  [C402H22]  45.57 81.69 0 bottom
C3104  SCD1U16V2KX-3DLGP  [C402H22]  100.19 114.88 0 bottom
C3107  SCD1U16V2KX-3DLGP  [C402H22]  49.05 79.97 180 top
C3108  SCD1U16V2KX-3DLGP  [C402H22]  44.45 81.69 270 bottom
C3109  SCD1U16V2KX-3DLGP  [C402H22]  100.95 114.88 0 bottom
C3110  SC4D7U6D3V3KX-DLGP  [C603H36]  45.27 84.86 180 bottom
C3112  SCD1U16V2KX-3DLGP  [C402H22]  48.13 83.92 90 bottom
C3115  SCD1U16V2KX-3DLGP  [C402H22]  44.45 83.28 270 bottom
C3116  SC15P50V2JN-DL-GP  [C402H22]  45.06 87.02 270 top
C3117  SCD1U16V2KX-3DLGP  [C402H22]  48.14 84.68 90 bottom
C3118  SCD1U16V2KX-3DLGP  [C402H22]  48.14 85.47 90 bottom
C3119  SCD1U16V2KX-3DLGP  [C402H22]  46.61 85.57 270 bottom
C3120  SCD1U16V2KX-3DLGP  [C402H22]  43.59 80.93 270 bottom
C3121  SCD1U16V2KX-3DLGP  [C402H22]  44.28 84.76 180 bottom
C3122  SC1U6D3V1MX-GP  [C0201H14]  47.6 86.72 180 bottom
C3123  SCD1U16V2KX-3DLGP  [C402H22]  50.68 86.79 0 bottom
C3124  SC4D7U6D3V3KX-DLGP  [C603H36]  46.54 81.15 0 bottom
C3125  SC15P50V2JN-DL-GP  [C402H22]  46.96 86.99 90 top
C3126  SC1U6D3V1MX-GP  [C0201H14]  44.45 82.48 270 bottom
C3202  SC100P3KV8JN-2-GP  [C1808H56]  24.75 84.05 90 bottom
C3203  SCD01U50V2KX-1DLGP  [C402H22]  39.12 84.25 0 bottom
C3507  SC1U10V2KX-1DLGP  [C402H22]  17.5 33.99 90 bottom
C3516  SCD1U16V2KX-3DLGP  [C402H22]  17.3 33.25 270 top
C3517  SC1U10V2KX-1DLGP  [C402H22]  17.3 34.01 270 top
C3518  SC22U6D3V3MX-1-DL-GP  [C603H40]  17.35 38.15 270 bottom
C3519  SC22U6D3V3MX-1-DL-GP  [C603H40]  16.94 35.61 180 bottom
C3520  SCD1U16V2KX-3DLGP  [C402H22]  22.84 54.18 90 bottom
C3521  SCD1U16V2KX-3DLGP  [C402H22]  22.84 53.42 90 bottom
C3522  SCD1U16V2KX-3DLGP  [C402H22]  22.08 44.93 90 bottom
C3523  SCD1U16V2KX-3DLGP  [C402H22]  22.08 44.15 90 bottom
C3524  SCD1U16V2KX-3DLGP  [C402H22]  16.56 56.87 180 bottom
C3525  SC1U10V2KX-1DLGP  [C402H22]  17.35 56.87 180 bottom
C3526  SC22U6D3V3MX-1-DL-GP  [C603H40]  20.27 56.44 180 bottom
C3527  SC22U6D3V3MX-1-DL-GP  [C603H40]  19.1 56.44 180 bottom
C3602  SCD1U16V2KX-3DLGP  [C402H22]  23.6 54.23 180 top
C4001  SC470P50V2KX-3GP  [C402H22]  44.38 132.28 270 top
C4002  SC470P50V2KX-3GP  [C402H22]  64.24 38.43 90 top
C4004  SC10U25V5KX-DL-GP  [C805H58]  57.28 118.39 225 bottom
C4005  SC10U6D3V3MX-DL-GP  [C603H36]  64.01 38.25 270 bottom
C4006  SC10U6D3V3MX-DL-GP  [C603H36]  108.04 118.92 90 top
C4007  SCD1U16V2KX-3DLGP  [C402H22]  107.16 125.5 270 top
C4008  SC10U6D3V3MX-DL-GP  [C603H36]  99.09 76.79 90 top
C4009  SC10U6D3V3MX-DL-GP  [C603H36]  146.23 71.07 0 top
C4010  SCD1U16V2KX-3DLGP  [C402H22]  100.79 72.7 0 top
C4011  SC470P50V2KX-3GP  [C402H22]  64.24 37.67 90 top
C4012  SC10U6D3V3MX-DL-GP  [C603H36]  116.31 115.37 270 top
C4013  SC10U6D3V3MX-DL-GP  [C603H36]  109.97 117.12 180 top
C4014  SC10U25V5KX-DL-GP  [C805H58]  48.01 81.34 0 bottom
C4015  SC10U6D3V3MX-DL-GP  [C603H36]  64.01 39.42 270 bottom
C4017  SC470P50V2KX-3GP  [C402H22]  44.17 133.05 270 top
C4031  SC1U10V2KX-1DLGP  [C402H22]  110.5 115.22 270 top
C4032  SC1U10V2KX-1DLGP  [C402H22]  108.94 120.4 90 top
C4033  SCD1U25V2KX-1-DL-GP  [C402H22]  110.06 122.48 0 top
C4034  SCD1U25V2KX-1-DL-GP  [C402H22]  113.59 115.19 90 bottom
C4035  SC22U6D3V3MX-1-DL-GP  [C603H40]  106.93 120.14 270 top
C4036  SC22U6D3V3MX-1-DL-GP  [C603H40]  108.76 117.12 180 top
C4041  SC1U10V2KX-1DLGP  [C402H22]  95.71 73.23 180 top
C4043  SC1U6D3V1MX-GP  [C0201H14]  99.52 75.77 90 top
C4301  SC1U50V3KX-1-GP  [C603H36]  26.87 129.02 0 top
C4302  SC1U50V3KX-1-GP  [C603H36]  25.96 123.93 90 top
C4303  SCD01U50V2KX-1DLGP  [C402H22]  32.77 133.35 180 top
C4304  SCD01U50V2KX-1DLGP  [C402H22]  31.25 133.35 180 top
C4305  SCD01U50V2KX-1DLGP  [C402H22]  32.01 133.35 180 top
C4306  SC10U25V5KX-DL-GP  [C805H58]  29.47 133.43 270 top
C4344  SC1KP50V2KX-1DLGP  [C402H22]  41.79 116.48 180 top
C4444  SC1500P50V2KX-2-DL-GP  [C402H22]  35.46 126.47 90 top
C5503  SC4D7U6D3V2MX-1-GP  [C402H22]  214.84 43.82 180 bottom
C5504  SC4D7U6D3V2MX-1-GP  [C402H22]  218.52 42.9 270 top
C5505  SC10U6D3V2MX-2-GP  [C402-TO0D2H28]  215.7 47.25 270 top
C5512  SCD1U25V2KX-GP  [C402H22]  216.91 37.89 0 top
C5513  SC1KP50V2KX-1DLGP  [C402H22]  216.15 37.87 0 top
C5514  SC10U25V5KX-DL-GP  [C805H58]  215.65 38.66 180 bottom
C5516  SCD1U25V2KX-GP  [C402H22]  160.76 108.03 180 bottom
C5517  SC10U6D3V2MX-2-GP  [C402-TO0D2H28]  159.16 108 180 bottom
C5520  SC4D7U6D3V2MX-1-GP  [C402H22]  154.42 106.76 90 bottom
C5521  SCD1U16V2KX-3GP  [C402H22]  215.19 55.05 270 bottom
C5522  SCD1U16V2KX-3GP  [C402H22]  215.19 52.69 270 bottom
C5523  SCD1U16V2KX-3GP  [C402H22]  215.19 51.92 270 bottom
C5524  SCD1U16V2KX-3GP  [C402H22]  215.19 54.26 270 bottom
C5525  SCD1U16V2KX-3GP  [C402H22]  215.19 53.5 270 bottom
C5526  SCD1U16V2KX-3GP  [C402H22]  215.19 55.81 270 bottom
C5528  SCD1U25V2KX-GP  [C402H22]  135.61 78.46 90 bottom
C5529  SCD1U16V2KX-3DLGP  [C402H22]  48.11 65.08 90 top
C5530  SCD1U16V2KX-3DLGP  [C402H22]  224.62 69.06 90 top
C5531  SC2200P50V2KX-2DLGP  [C402H22]  137.8 92.33 270 bottom
C5535  SC2200P50V2KX-2DLGP  [C402H22]  221.69 67.95 270 top
C5536  SC1U6D3V1MX-GP  [C0201H14]  217.66 40.67 180 top
C5538  SCD1U16V2KX-3DLGP  [C402H22]  218.29 40.67 180 top
C5539  SC470P50V2KX-3GP  [C402H22]  159.64 104.93 270 bottom
C5540  SC470P50V2KX-3GP  [C402H22]  159.64 105.69 270 bottom
C5541  SC1U6D3V1MX-GP  [C0201H14]  217.15 40.67 180 top
C5599  SC4D7U6D3V2MX-1-GP  [C402H22]  219.05 40.67 180 top
C5724  SCD01U50V2KX-1GP  [C402H22]  21.8 100.81 0 bottom
C5736  SCD1U16V2KX-3DLGP  [C402H22]  17.28 102.08 270 top
C5777  SCD1U16V2KX-3GP  [C402H22]  24.41 95.05 90 bottom
C5778  SCD1U16V2KX-3GP  [C402H22]  24.41 94.26 90 bottom
C5779  SCD1U16V2KX-3GP  [C402H22]  23.8 97.11 90 bottom
C5780  SCD1U16V2KX-3GP  [C402H22]  23.8 96.32 90 bottom
C5781  SCD1U16V2KX-3GP  [C402H22]  24.56 99.11 90 bottom
C5782  SCD1U16V2KX-3GP  [C402H22]  24.56 98.32 90 bottom
C5783  SCD1U16V2KX-3GP  [C402H22]  25.17 101.22 90 bottom
C5784  SCD1U16V2KX-3GP  [C402H22]  25.17 100.43 90 bottom
C5801  SCD1U16V2KX-3DLGP  [C402H22]  49.89 112.12 180 top
C5802  SCD1U16V2KX-3DLGP  [C402H22]  50.65 112.12 180 top
C5803  SCD1U16V2KX-3DLGP  [C402H22]  46.38 111.58 180 top
C5804  SCD1U16V2KX-3DLGP  [C402H22]  47.15 111.58 180 top
C5805  SCD1U16V2KX-3DLGP  [C402H22]  61.55 116.92 90 bottom
C5806  SCD1U16V2KX-3DLGP  [C402H22]  61.55 117.68 90 bottom
C5807  SCD1U16V2KX-3DLGP  [C402H22]  63.33 115.39 90 bottom
C5808  SCD1U16V2KX-3DLGP  [C402H22]  63.33 116.16 90 bottom
C5809  SCD1U25V2KX-GP  [C402H22]  52.61 117.98 180 bottom
C5810  SCD01U25V2KX-3DLGP  [C402H22]  45.37 119.99 0 top
C5811  SCD1U16V2KX-3DLGP  [C402H22]  43.82 115.44 270 top
C5812  SCD1U16V2KX-3DLGP  [C402H22]  56.34 115.27 90 top
C5813  SCD1U16V2KX-3DLGP  [C402H22]  55.32 119.48 45 bottom
C5854  SCD1U16V2KX-3DLGP  [C402H22]  57.43 116.79 270 top
C5862  SCD1U16V2KX-3DLGP  [C402H22]  57.43 116.03 270 top
C5863  SC2D2U10V2KX-GP  [C402H22]  52.99 113.89 90 bottom
C6007  SCD1U16V2KX-3DLGP  [C402H22]  156.59 39.04 270 top
C6008  SC10U10V2MX-DL-GP-U  [C402-TO0D2H28]  158.37 39.42 180 top
C6010  SCD01U25V2KX-3DLGP  [C402H22]  189.11 39.55 270 top
C6011  SCD01U25V2KX-3DLGP  [C402H22]  189.11 38.79 270 top
C6013  SCD01U25V2KX-3DLGP  [C402H22]  191.72 39.63 180 top
C6014  SCD01U25V2KX-3DLGP  [C402H22]  192.48 39.63 180 top
C6018  SC10U10V2MX-DL-GP-U  [C402-TO0D2H28]  187.12 33.9 0 top
C6019  SCD1U16V2KX-3DLGP  [C402H22]  186.28 33.85 0 top
C6028  SCD01U25V2KX-3DLGP  [C402H22]  165.36 38.79 180 top
C6029  SCD01U25V2KX-3DLGP  [C402H22]  164.6 38.79 180 top
C6030  SCD01U25V2KX-3DLGP  [C402H22]  163.71 38.79 180 top
C6031  SCD01U25V2KX-3DLGP  [C402H22]  162.94 38.79 180 top
C6102  SC4D7U6D3V3KX-L-GP  [C603H36]  47.76 102.29 270 top
C6104  SCD1U16V2KX-3DLGP  [C402H22]  31.42 105.23 180 top
C6105  SC10U6D3V3MX-DL-GP  [C603H36]  29.7 105.21 180 top
C6106  SCD1U25V2KX-1-DL-GP  [C402H22]  30.66 105.23 180 top
C6107  SCD1U16V2KX-3DLGP  [C402H22]  40.07 94.95 180 bottom
C6108  SCD1U16V2KX-3DLGP  [C402H22]  39.29 94.95 180 bottom
C6201  SCD1U16V2KX-3DLGP  [C402H22]  214.96 61.13 90 top
C6202  SCD1U16V2KX-3DLGP  [C402H22]  214.96 61.89 90 top
C6302  SCD22U10V2KX-2-GP  [C402H22]  24.31 35.08 0 bottom
C6303  SCD22U10V2KX-2-GP  [C402H22]  25.07 35.08 0 bottom
C6304  SC33P50V2JN-3DLGP  [C402H22]  20.4 21.59 90 top
C6305  SC33P50V2JN-3DLGP  [C402H22]  20.4 22.35 90 top
C6306  SCD047U25V2KX-4-GP  [C402H22]  39.65 30.43 0 bottom
C6307  SCD1U16V2KX-3DLGP  [C402H22]  38.87 30.43 0 bottom
C6308  SCD047U25V2KX-4-GP  [C402H22]  20.4 23.12 90 top
C6311  SCD22U10V2KX-2-GP  [C402H22]  27.31 35.41 0 bottom
C6312  SCD22U10V2KX-2-GP  [C402H22]  28.07 35.41 0 bottom
C6313  SCD22U10V2KX-2-GP  [C402H22]  30.31 35.6 0 bottom
C6314  SCD22U10V2KX-2-GP  [C402H22]  31.07 35.6 0 bottom
C6315  SCD22U10V2KX-2-GP  [C402H22]  33.33 35.08 0 bottom
C6316  SCD22U10V2KX-2-GP  [C402H22]  34.09 35.08 0 bottom
C6317  SC10U6D3V3MX-DL-GP  [C603H36]  40.21 28.49 180 bottom
C6318  SC10U6D3V3MX-DL-GP  [C603H36]  39.02 28.49 180 bottom
C6401  SCD1U16V2KX-3DLGP  [C402H22]  210.37 56.44 270 bottom
C6405  SC2D2U6D3V2MX-DL-GP  [C402H22]  50.98 68.2 180 top
C6501  SCD1U16V2KX-3GP  [C402H22]  85.39 37.69 90 top
C6502  SCD1U16V2KX-3DLGP  [C402H22]  93.25 32.21 180 bottom
C6505  SCD1U16V2KX-3GP  [C402H22]  102.49 29.16 180 top
C6506  SC10P50V2JN-4DLGP  [C402H22]  100.51 34.29 180 bottom
C6510  SC10P50V2JN-4DLGP  [C402H22]  88.45 37.72 90 top
C6511  SC10P50V2JN-4DLGP  [C402H22]  108.21 40.31 180 top
C7003  SCD1U16V2KX-3DLGP  [C402H22]  136.5 94.41 270 bottom
C7004  SC10U6D3V3MX-GP  [C603H38]  136.55 93.45 270 bottom
C7103  SCD1U16V2KX-3DLGP  [C402H22]  27.44 101.14 270 top
C7104  SCD1U16V2KX-3DLGP  [C402H22]  27.44 100.38 270 top
C7105  SCD1U16V2KX-3DLGP  [C402H22]  27.82 99.37 270 top
C7106  SCD1U16V2KX-3DLGP  [C402H22]  27.82 98.6 270 top
C7107  SCD1U16V2KX-3DLGP  [C402H22]  27.26 105.28 270 top
C7108  SCD1U16V2KX-3DLGP  [C402H22]  27.28 106.83 270 top
C7109  SCD1U16V2KX-3DLGP  [C402H22]  27.28 106.07 270 top
C7110  SCD1U16V2KX-3DLGP  [C402H22]  27.26 108.43 270 top
C7111  SCD1U16V2KX-3DLGP  [C402H22]  27.26 107.65 270 top
C7112  SCD1U16V2KX-3DLGP  [C402H22]  27.28 102.97 270 top
C7113  SCD1U16V2KX-3DLGP  [C402H22]  27.28 103.73 270 top
C7114  SCD1U16V2KX-3DLGP  [C402H22]  27.26 104.52 270 top
C7115  SCD1U16V2KX-3DLGP  [C402H22]  21.75 103.33 180 bottom
C7116  SCD1U16V2KX-3DLGP  [C402H22]  20.04 107.54 0 bottom
C7117  SCD1U16V2KX-3DLGP  [C402H22]  22.51 103.33 180 bottom
C7118  SCD1U16V2KX-3DLGP  [C402H22]  22.89 108.56 270 bottom
C7119  SC10U6D3V3MX-DL-GP  [C603H36]  21.09 107.82 180 bottom
C7120  SCD1U16V2KX-3DLGP  [C402H22]  33.94 121.46 180 top
C7161  SCD1U25V2KX-1-DL-GP  [C402H22]  17.58 104.09 90 top
C7162  SCD1U25V2KX-1-DL-GP  [C402H22]  17.58 104.85 90 top
C7163  SCD1U25V2KX-1-DL-GP  [C402H22]  17.58 105.72 90 top
C7164  SCD1U25V2KX-1-DL-GP  [C402H22]  17.58 106.5 90 top
C7165  SC2D2U6D3V2MX-DL-GP  [C402H22]  18.8 101.88 90 top
C7166  SCD1U25V2KX-1-DL-GP  [C402H22]  23.42 107.04 270 bottom
C7167  SCD33U6D3V1MX-GP  [C0201H13]  17.33 103.28 270 top
C7168  SCD33U6D3V1MX-GP  [C0201H13]  17.45 108.29 270 top
C7169  SCD33U6D3V1MX-GP  [C0201H13]  17.45 107.75 270 top
C7170  SCD33U6D3V1MX-GP  [C0201H13]  17.33 102.74 270 top
C7201  SCD1U25V2KX-1-DL-GP  [C402H22]  45.98 109.27 0 top
C7202  SC1U6D3V1MX-GP  [C0201H14]  41.79 107.19 0 top
C7203  SCD1U16V2KX-3DLGP  [C402H22]  38.49 106.03 270 top
C7204  SCD1U16V2KX-3DLGP  [C402H22]  38.49 107.63 270 top
C7205  SCD1U16V2KX-3DLGP  [C402H22]  43.96 125.45 180 top
C7206  SC10U6D3V2MX-2-GP  [C402-TO0D2H28]  44.87 125.54 180 top
C7207  SC1U10V2KX-1DLGP  [C402H22]  38.49 106.82 270 top
C7208  SC390P50V2KX-GP-U  [C402H24]  44.3 111.89 180 top
C7209  SC390P50V2KX-GP-U  [C402H24]  43.82 110.42 0 top
C7210  SCD1U16V2KX-3DLGP  [C402H22]  39.96 105.16 270 top
C7211  SCD1U16V2KX-3DLGP  [C402H22]  41.45 105.93 90 top
C7212  SC1U10V2KX-1DLGP  [C402H22]  41.45 105.14 90 top
C7213  SCD1U16V2KX-3DLGP  [C402H22]  43.69 113.06 90 top
C7214  SC1U50V3KX-GP  [C603H32]  49.75 127.04 90 top
C7215  SCD22U10V2KX-1GP  [C402H22]  59.21 135.21 270 top
C7216  SCD1U16V2KX-3DLGP  [C402H22]  52.16 129.01 180 top
C7217  SC2D2U6D3V2MX-DL-GP  [C402H22]  53.15 129.27 180 top
C7302  SCD1U25V2KX-1-DL-GP  [C402H22]  9.81 125.1 0 bottom
C7303  SCD1U25V2KX-1-DL-GP  [C402H22]  11.84 118.9 270 bottom
C7304  SCD1U25V2KX-1-DL-GP  [C402H22]  11.15 124.33 180 bottom
C7305  SC10U25V5KX-DL-GP  [C805H58]  12.35 113.54 270 bottom
C7306  SC1U50V3KX-1-GP  [C603H36]  12.02 120.35 90 top
C7307  SCD1U25V2KX-1-DL-GP  [C402H22]  11.84 118.11 270 bottom
C7401  SC1500P50V2KX-2-DL-GP  [C402H22]  33.57 124.27 0 top
C7403  SC22U6D3V3MX-1-DL-GP  [C603H40]  45.72 123.3 90 top
C7404  SC22U6D3V3MX-1-DL-GP  [C603H40]  44.99 122.1 90 top
C7405  SC1KP50V2KX-1GP  [C402H22]  39.18 120.6 0 top
C7601  SCD22U10V2KX-1GP  [C402H22]  122.24 139.61 225 bottom
C7602  SCD22U10V2KX-1GP  [C402H22]  121.68 139.05 225 bottom
C7603  SCD22U10V2KX-1GP  [C402H22]  122.81 140.17 225 bottom
C7604  SCD22U10V2KX-1GP  [C402H22]  123.36 140.73 225 bottom
C7605  SCD22U10V2KX-1GP  [C402H22]  123.94 141.3 225 bottom
C7606  SCD22U10V2KX-1GP  [C402H22]  124.48 141.85 225 bottom
C7607  SCD22U10V2KX-1GP  [C402H22]  125.04 142.41 225 bottom
